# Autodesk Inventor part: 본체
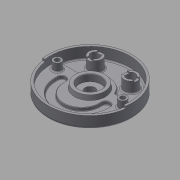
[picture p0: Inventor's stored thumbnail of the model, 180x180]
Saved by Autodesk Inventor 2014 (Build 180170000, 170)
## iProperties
Created: 2015-06
Part Number: 본체
Material: Generic
Document SubType Name: Modeling
Designer: MYHOME
Density: 1 g/cm^3
Appearance: Default
Author: MYHOME
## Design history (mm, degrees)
sketch "스케치16"
  geometry: C1 r 95 at (0, 0); 1 further point
  constraints: 1 centre point, 1 coincident
  dimensions: "d45" = 95 radius of C1
extrude "돌출11" new body sketch "스케치16" distance "d46" = 32; taper "d47" = 0 deg
sketch "스케치18"
  geometry: C1 r 95 at (0, 0) reference; C2 r 26 at (0, 0)
  constraints: 1 centre point, 1 coincident
  dimensions: "d51" = 26 radius of C2
extrude "돌출13" join sketch "스케치18" distance "d52" = 12; taper "d53" = -15 deg
sketch "스케치24"
  geometry: C1 r 95 at (0, 0) reference; C2 r 90 at (0, 0)
  constraints: 1 centre point, 1 coincident
  dimensions: "d84" = 90 radius of C2
extrude "돌출17" cut sketch "스케치24" distance "d85" = 25; taper "d86" = 0 deg
sketch "스케치25"
  geometry: L1 (-88.566, 16)-(88.566, 16); C1 r 42 at (0, 0); A1 r 90 centre (0, 0) between (-88.566, 16) and (88.566, 16) reference
  constraints: 2 end point, 2 point on circle, 1 centre point, 1 coincident, 1 horizontal
  dimensions: "d87" = 42 radius of C1; "d88" = 16 distance from line of L1 C1.centre
extrude "돌출18" join sketch "스케치25" distance "d89" = 7; taper "d90" = 0 deg
sketch "스케치26"
  geometry: L1 (88.566, 16)-(38.833, 16) reference; L2 (50, -19)-(50, -14); L3 (41, -19)-(41, -14); L4 (59, -19)-(59, -14); L5 (-50, -19)-(-50, -14); L6 (-59, -19)-(-59, -14); L7 (-41, -19)-(-41, -14); A1 r 90 centre (0, 0) between (-88.566, 16) and (88.566, 16) reference; A2 r 50 centre (0, -19) between (-50, -19) and (50, -19); A3 r 59 centre (0, -19) between (-59, -19) and (59, -19); A4 r 41 centre (0, -19) between (-41, -19) and (41, -19); A5 r 9 centre (-50, -19) between (-41, -19) and (-59, -19); A6 r 9 centre (50, -19) between (59, -19) and (41, -19); A7 r 9 centre (50, -14) between (41, -14) and (59, -14); A8 r 9 centre (-50, -14) between (-59, -14) and (-41, -14)
  constraints: 15 point on circle, 12 end point, 11 tangent, 7 centre point, 2 coincident, 2 horizontal alignment, 2 parallel, 1 perpendicular, 1 vertical alignment
  dimensions: "d91" = 19 distance of A2.centre A1.centre; "d92" = 41 radius of A4; "d93" = 18 radial gap between concentric circles of A3 A4; "d94" = 5 distance of L2.start L2.end; "d95" = 9 radius of A7; "d96" = 5 distance of L5.start L5.end; "d97" = 9 radius of A8
extrude "돌출19" cut sketch "스케치26" distance "d98" = 7; taper "d99" = 0 deg
fillet "모깎기3" dims "d100" = 10
sketch "스케치27"
  geometry: C1 r 35 at (0, 0); A1 r 42 centre (0, 0) between (38.833, 16) and (-38.833, 16) reference
  constraints: 1 centre point, 1 coincident
  dimensions: "d101" = 35 radius of C1
extrude "돌출20" join sketch "스케치27" distance "d102" = 10; taper "d103" = -10 deg
sketch "스케치28"
  geometry: C1 r 33.237 at (0, 0) reference; C2 r 25 at (0, 0)
  constraints: 1 centre point, 1 coincident
  dimensions: "d104" = 25 radius of C2
extrude "돌출21" cut sketch "스케치28" distance "d105" = 15; taper "d106" = 0 deg
sketch "스케치29"
  geometry: C1 r 25 at (0, 0) reference; C2 r 11.5 at (0, 0)
  constraints: 1 centre point, 1 coincident
  dimensions: "d107" = 11.5 radius of C2
extrude "돌출22" cut sketch "스케치29" stored distance "d108" = 15; taper "d109" = 0 deg
sketch "스케치31"
  geometry: C1 r 15 at (-40, 52); C2 r 15 at (40, 52); A1 r 90 centre (0, 0) between (85.114, 29.25) and (-85.114, 29.25) reference
  constraints: 2 centre point
  dimensions: "d111" = 15 radius of C1; "d112" = 15 radius of C2; "d113" = 52 vertical distance of C2.centre A1.centre; "d114" = 52 vertical distance of C1.centre A1.centre; "d115" = 40 horizontal distance of A1.centre C1.centre; "d116" = 40 horizontal distance of C2.centre A1.centre
extrude "돌출23" join sketch "스케치31" distance "d117" = 25; taper "d118" = 0 deg
sketch "스케치32"
  geometry: C1 r 15 at (0, 0) reference; C2 r 15 at (80, 0) reference; C3 r 10 at (0, 0); C4 r 10 at (80, 0); 1 further point
  constraints: 2 centre point, 2 coincident
  dimensions: "d119" = 10 radius of C3; "d120" = 10 radius of C4
extrude "돌출24" cut sketch "스케치32" stored distance "d121" = 25; taper "d122" = 0 deg
sketch "스케치38"
  geometry: C1 r 10 at (40, 52) reference; C2 r 10 at (-40, 52) reference; C3 r 26 at (0, 0) reference; C4 r 9 at (-74, 0); C5 r 9 at (74, 0)
  constraints: 2 centre point
  dimensions: "d146" = 9 radius of C4; "d147" = 9 radius of C5; "d148" = 52 vertical distance of C4.centre C2.centre; "d149" = 52 vertical distance of C5.centre C1.centre; "d150" = 74 distance of C3.centre C4.centre; "d151" = 74 distance of C5.centre C3.centre
extrude "돌출27" cut sketch "스케치38" distance "d152" = 11; taper "d153" = 0 deg
sketch "스케치40"
  geometry: C1 r 35 at (0, 0) reference; C2 r 9 at (-74, 0); C3 r 9 at (74, 0); A1 r 10 centre (-40, 52) between (-46, 60) and (-46, 44) reference; A2 r 10 centre (40, 52) between (50, 52) and (50, 52) reference
  constraints: 2 centre point
  dimensions: "d156" = 9 radius of C2; "d157" = 9 radius of C3; "d158" = 74 distance of C1.centre C2.centre; "d159" = 74 distance of C3.centre C1.centre; "d160" = 52 vertical distance of A1.centre C2.centre; "d161" = 52 vertical distance of A2.centre C3.centre
extrude "돌출28" join sketch "스케치40" distance "d162" = 18; taper "d163" = 0 deg
sketch "스케치43"
  geometry: C1 r 9 at (0, 0) reference; C2 r 5.5 at (0, 0); C3 r 5.5 at (148, 0); C4 r 10 at (114, 52) reference; 1 further point
  constraints: 2 centre point, 1 coincident
  dimensions: "d164" = 5.5 radius of C2; "d165" = 5.5 radius of C3; "d166" = 74 distance of C3.centre point (74, 0); "d167" = 52 vertical distance of C4.centre C3.centre
extrude "돌출29" cut sketch "스케치43" stored distance "d168" = 18; taper "d169" = 0 deg
sketch "스케치44"
  geometry: L1 (-95, 0)-(0, 0); L2 (0, 0)-(-89.124, -12.526); L3 (0, 0)-(95, 0); L4 (0, 0)-(89.124, -12.526); L5 (-89.124, -12.526)-(-94.075, -13.221); L6 (89.124, -12.526)-(94.075, -13.221); A1 r 90 centre (0, 0) between (-89.024, -13.221) and (89.024, -13.221) reference; A2 r 95 centre (0, 0) between (-95, 0) and (-94.075, -13.221) reference
  constraints: 12 end point, 8 point on circle, 1 collinear, 1 horizontal
  dimensions: "d170" = 8 deg angle of L1 L2; "d172" = 8 deg angle of L3 L4; "d173" = 8 deg angle of L3 L6; "d174" = 8 deg angle of L1 L5
extrude "돌출30" cut sketch "스케치44" distance "d175" = 5; taper "d176" = 0 deg
sketch "스케치46"
  geometry: C1 r 95 at (0, 0) reference; C2 r 68 at (0, 0)
  constraints: 1 centre point, 1 coincident, 1 other
  dimensions: "d178" = 68 radius of C2
feature "엠보싱1" sketch "스케치46" dims "d46" = 32, "d87" = 42, "d88" = 16, "d180" = 0.5, "d181" = 0
fillet "모깎기6" dims "d184" = 3
chamfer "모따기1" distance "d185" = 1; stored, may be unused: second distance "d186" = 2, angle "d187" = 45 deg
fillet "모깎기7" dims "d188" = 0.3
sketch "스케치48"
  geometry: L1 (6, -19)-(-6, -19); L2 (-6, -19)-(-6, 19); L3 (-6, 19)-(6, 19); L4 (6, 19)-(6, -19); L5 (6, -19)-(-6, 19); L6 (-6, -19)-(6, 19); C1 r 15 at (0, 0) reference; 1 further point
  constraints: 12 end point, 2 midpoint, 2 parallel, 1 horizontal, 1 perpendicular
  dimensions: "d192" = 12 distance between parallel lines of L4 L2; "d193" = 38 distance between parallel lines of L1 L3
extrude "돌출32" cut sketch "스케치48" distance "d194" = 3; taper "d195" = 0 deg
sketch "스케치49"
  geometry: L1 (21, -6)-(-21, -6); L2 (-21, -6)-(-21, 6); L3 (-21, 6)-(21, 6); L4 (21, 6)-(21, -6); L5 (21, -6)-(-21, 6); L6 (-21, -6)-(21, 6); C1 r 15 at (0, 0) reference; 1 further point
  constraints: 12 end point, 2 midpoint, 2 parallel, 1 horizontal, 1 perpendicular
  dimensions: "d196" = 12 distance between parallel lines of L1 L3; "d197" = 42 distance between parallel lines of L4 L2
extrude "돌출33" cut sketch "스케치49" distance "d198" = 3; taper "d199" = 0 deg
fillet "모깎기8" dims "d200" = 5
fillet "모깎기9" dims "d201" = 1
chamfer "모따기2" distance "d202" = 1; stored, may be unused: second distance "d203" = 2, angle "d204" = 45 deg
fillet "모깎기10" dims "d205" = 3
fillet "모깎기12" dims "d207" = 3
fillet "모깎기13" dims "d208" = 3
node "솔리드2"
other parameters: "d58" = 16, "d65" = 52, "d66" = 16, "d71" = 52, "d131" = 6, "d132" = 6
